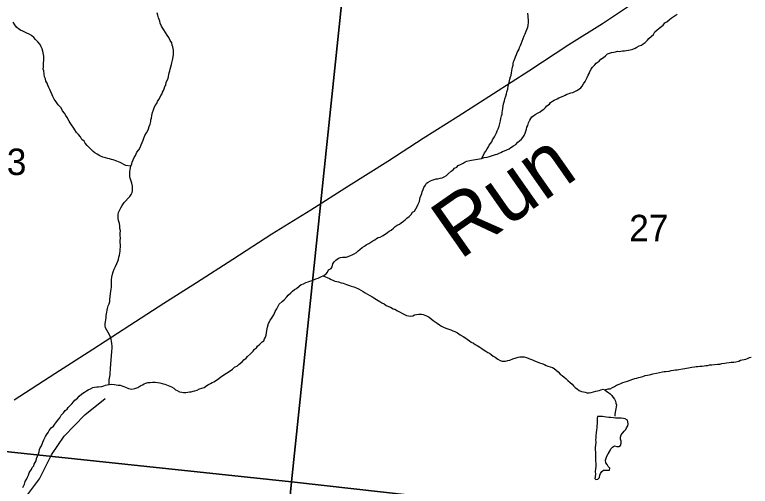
# Model space of a CAD drawing. Extents: x 1310247 to 1664935, y 284496 to 704931.
# Drawn here: x 1488010 to 1494175, y 510491 to 514440 of the extents above; entities that cross this region are included whole.
import ezdxf

# ---------------------------------------------------------------- set-up
doc = ezdxf.new("R2010")
doc.units = 0
for name, color, linetype in [('GM_X_County', 7, 'Continuous'), ('GM_X_County_Subdivision_Text', 7, 'Continuous'), ('GM_X_Minor_Lake_Text', 7, 'Continuous'), ('GM_X_Minor_River', 7, 'Continuous'), ('GM_X_Minor_River_Text', 7, 'Continuous'), ('GM_X_State_Shield', 7, 'Continuous'), ('GM_X_US_Location', 7, 'Continuous')]:
    doc.layers.add(name, color=color, linetype=linetype)

msp = doc.modelspace()

# ---------------------------------------------------------------- linework, layer by layer
at = {"layer": 'GM_X_County'}
for points in [[(1485560.1, 516006.4), (1490846.7, 515461.6), (1490330.6, 510528.2), (1485056.1, 511086.7)], [(1490846.7, 515461.6), (1496329.6, 514931.2), (1495825.8, 509911.6), (1490330.6, 510528.2)], [(1485056.1, 511086.7), (1490330.6, 510528.2), (1489787.4, 504902.9), (1486694.2, 505230.8), (1484474.7, 505338.4)], [(1490330.6, 510528.2), (1495825.8, 509911.6), (1495258.9, 504406.3), (1489787.4, 504902.9)]]:
    msp.add_lwpolyline(points, close=True, dxfattribs=at)
at = {"layer": 'GM_X_County_Subdivision_Text'}
msp.add_lwpolyline([(1488033.7, 510094), (1488042.5, 510123.8), (1488071.6, 510290), (1488089, 510365.9), (1488109.8, 510407.7), (1488218.9, 510554.4), (1488318.8, 510753.5), (1488424.1, 510912.3), (1488598, 511090.1), (1488769.2, 511227.7)], dxfattribs=at)
at = {"layer": 'GM_X_Minor_River'}
msp.add_line((1492872.4, 510557.4), (1492880.1, 510547.1), dxfattribs=at)
msp.add_lwpolyline([(1492880.1, 510547.1), (1492898.3, 510550.6), (1492910.8, 510564.2), (1492915.5, 510584.1), (1492920, 510598), (1492930.6, 510615.7), (1492945, 510625.3), (1492963.1, 510626.7), (1492977.2, 510626.3), (1492995.2, 510625.7), (1492997.8, 510641.7), (1492984.2, 510656.1), (1492976.7, 510672.4), (1492965.2, 510688.8), (1492961.8, 510708.9), (1492966.4, 510726.8), (1492973, 510744.6), (1492983.7, 510762.3), (1492992.2, 510776.1), (1493000.7, 510791.8), (1493007.2, 510805.7), (1493019.7, 510819.3), (1493038.1, 510828.8), (1493058, 510824.2), (1493074.2, 510825.7), (1493088.5, 510833.2), (1493093.1, 510851.1), (1493093.7, 510869.1), (1493088.2, 510885.3), (1493086.8, 510903.4), (1493093.4, 510921.2), (1493106, 510938.9), (1493118.6, 510952.5), (1493131.1, 510966.2), (1493137.5, 510980), (1493148.2, 510997.7), (1493150.7, 511011.6), (1493149.2, 511029.7), (1493145.7, 511043.8), (1493128, 511056.4), (1493114, 511058.8), (1493094, 511061.5), (1493080, 511061.9), (1493065.9, 511062.3), (1493045.8, 511063), (1493027.8, 511065.5), (1493003.8, 511066.2), (1492989.7, 511066.7), (1492969.8, 511071.3), (1492951.8, 511073.9), (1492937.7, 511074.3), (1492917.7, 511076.9), (1492895.6, 511075.6), (1492893.1, 511061.6), (1492892.6, 511045.6), (1492892, 511027.6), (1492891.5, 511013.6), (1492889, 510999.6), (1492888.4, 510981.6), (1492885.8, 510963.7), (1492885, 510937.7), (1492882.3, 510917.7), (1492881.6, 510895.7), (1492879, 510879.7), (1492880.5, 510863.7), (1492877.5, 510831.7), (1492875, 510817.8), (1492876.3, 510795.7), (1492877.6, 510775.6), (1492877, 510757.6), (1492878.5, 510741.5), (1492878, 510725.5), (1492879.3, 510705.4), (1492880.5, 510681.4), (1492880.1, 510667.3), (1492879.6, 510653.3), (1492879.1, 510639.3), (1492876.3, 510613.4), (1492877.7, 510595.3), (1492874.9, 510571.3), (1492872.4, 510557.4)], dxfattribs=at)
at = {"layer": 'GM_X_Minor_River_Text'}
for points in [[(1488995.4, 513205.1), (1489004.1, 513224.8), (1489012.8, 513244.6), (1489021.4, 513260.4), (1489027.8, 513274.2), (1489034.4, 513290), (1489051.1, 513309.5), (1489061.8, 513329.3), (1489070.6, 513351), (1489079.3, 513370.8), (1489085.9, 513390.6), (1489092.5, 513406.5), (1489101.2, 513428.2), (1489114, 513449.9), (1489124.8, 513471.6), (1489131.3, 513485.4), (1489137.9, 513505.2), (1489144.6, 513525.1), (1489151.4, 513546.9), (1489151.8, 513560.9), (1489156.3, 513574.8), (1489159.1, 513596.8), (1489165.9, 513620.6), (1489172.6, 513642.4), (1489179.2, 513660.2), (1489187.9, 513680), (1489200.6, 513697.6), (1489207.1, 513713.5), (1489217.7, 513729.2), (1489230.5, 513750.8), (1489234.9, 513764.7), (1489245.4, 513778.4), (1489249.9, 513792.3), (1489256.4, 513806.1), (1489262.9, 513820), (1489269.5, 513837.8), (1489276, 513851.6), (1489280.8, 513875.5), (1489291.5, 513895.2), (1489296, 513909.1), (1489300.4, 513923), (1489303, 513939), (1489305.5, 513954.9), (1489310.1, 513970.8), (1489312.5, 513984.7), (1489319.2, 514004.6), (1489323.8, 514022.5), (1489326.3, 514036.4), (1489333.1, 514060.2), (1489335.6, 514074.2), (1489338, 514088.1), (1489340.7, 514108.1), (1489341.4, 514128.1), (1489341.8, 514142.1), (1489338.4, 514158.3), (1489336.8, 514172.3), (1489331.3, 514186.5), (1489325.8, 514204.7), (1489314.4, 514225.1), (1489301.2, 514249.6), (1489287.8, 514270), (1489274.5, 514292.5), (1489261.1, 514312.9), (1489247.6, 514329.3), (1489240.1, 514345.6), (1489230.8, 514369.9), (1489225.3, 514386.1), (1489214.2, 514414.5), (1489208.9, 514436.7), (1489205.5, 514454.9)], [(1491924.1, 513237.2), (1491947.7, 513282.6), (1491958.3, 513298.3), (1491968.9, 513316), (1491981.5, 513333.7), (1491988, 513347.5), (1491998.6, 513363.2), (1492009.1, 513376.9), (1492015.6, 513392.7), (1492030.5, 513416.3), (1492041.1, 513434), (1492049.7, 513449.8), (1492054.3, 513467.7), (1492062.9, 513485.4), (1492069.7, 513507.3), (1492076.4, 513529.1), (1492081.2, 513553), (1492085.8, 513570.9), (1492090.6, 513594.8), (1492095.1, 513608.7), (1492095.6, 513622.7), (1492098.1, 513638.6), (1492100.7, 513654.6), (1492105.3, 513674.5), (1492108, 513694.4), (1492114.9, 513720.2), (1492119.4, 513736.1), (1492126.2, 513758), (1492130.8, 513777.9), (1492135.4, 513793.8), (1492142.2, 513817.6), (1492145.1, 513845.5), (1492154, 513871.3), (1492161, 513901.2), (1492165.7, 513919), (1492170.2, 513934.9), (1492172.8, 513952.9), (1492177.4, 513970.8), (1492179.9, 513986.7), (1492182.4, 514000.7), (1492187, 514016.6), (1492189.4, 514030.5), (1492191.9, 514044.5), (1492196.4, 514058.3), (1492207.4, 514088.1), (1492216.1, 514107.8), (1492222.6, 514123.7), (1492229.1, 514137.5), (1492237.7, 514153.2), (1492242.2, 514167.1), (1492248.7, 514183), (1492255.2, 514196.8), (1492264, 514218.6), (1492272.8, 514242.3), (1492281.5, 514262.1), (1492288.1, 514279.9), (1492296.8, 514301.7), (1492305.6, 514323.5), (1492310.1, 514337.4), (1492314.6, 514351.2), (1492317.5, 514379.2), (1492316.2, 514401.3), (1492314.7, 514415.4), (1492313.1, 514429.4), (1492309.9, 514453.6)], [(1492872.3, 514019.5), (1492884.8, 514035.2), (1492907.5, 514052.5), (1492924.1, 514068), (1492944.7, 514083.4), (1492961.1, 514094.9), (1492977.8, 514112.4), (1492994.1, 514118), (1493012.3, 514123.4), (1493030.5, 514126.9), (1493046.7, 514130.4), (1493062.9, 514133.9), (1493076.9, 514133.4), (1493091.1, 514135), (1493105.2, 514136.6), (1493121.3, 514138.1), (1493135.4, 514139.7), (1493153.6, 514143.1), (1493167.8, 514146.7), (1493190.1, 514152), (1493210.4, 514159.4), (1493224.8, 514169), (1493243.2, 514178.4), (1493263.5, 514185.8), (1493278, 514197.4), (1493294.4, 514208.9), (1493315.2, 514228.3), (1493325.7, 514242), (1493348.4, 514261.3), (1493362.9, 514274.9), (1493375.7, 514296.5), (1493392.3, 514312.1), (1493410.9, 514327.5), (1493443.9, 514352.5), (1493460.6, 514372.1), (1493476.9, 514379.6), (1493497.7, 514401), (1493512.1, 514410.6), (1493528.5, 514422.1), (1493563.5, 514445)], [(1488982.3, 513173.4), (1488940.3, 513178.7), (1488924.5, 513187.2), (1488906.7, 513195.8), (1488892.8, 513202.2), (1488865.1, 513215.1), (1488835.3, 513224), (1488821.4, 513228.5), (1488805.5, 513233), (1488789.5, 513237.5), (1488771.6, 513242), (1488749.7, 513248.7), (1488723.9, 513259.5), (1488700.3, 513272.2), (1488682.5, 513282.8), (1488668.9, 513295.3), (1488651.3, 513311.8), (1488631.9, 513330.5), (1488616.3, 513345), (1488600.8, 513363.5), (1488591.3, 513381.8), (1488573.7, 513396.4), (1488560.4, 513418.8), (1488545, 513437.3), (1488529.4, 513453.8), (1488514.1, 513476.3), (1488504.5, 513490.7), (1488485.3, 513517.3), (1488475.8, 513533.6), (1488466.3, 513549.9), (1488449.2, 513578.5), (1488437.7, 513596.9), (1488426.3, 513615.3), (1488410.9, 513635.8), (1488399.6, 513660.2), (1488374.3, 513685), (1488359, 513709.5), (1488341.8, 513734.1), (1488330.5, 513756.5), (1488324.9, 513770.7), (1488313.6, 513795.1), (1488304.3, 513815.4), (1488296.7, 513829.6), (1488287.3, 513850), (1488281.8, 513866.2), (1488272.3, 513882.5), (1488267, 513902.7), (1488259.5, 513921), (1488256.3, 513943.1), (1488255.1, 513969.2), (1488249.5, 513983.4), (1488250.2, 514003.4), (1488251, 514027.4), (1488251.5, 514041.4), (1488253.9, 514055.4), (1488254.7, 514077.4), (1488253.2, 514093.5), (1488251.6, 514107.5), (1488248.1, 514121.7), (1488246.5, 514135.7), (1488241.1, 514153.9), (1488231.7, 514172.3), (1488224.2, 514190.5), (1488204.9, 514213.1), (1488185.5, 514233.8), (1488170, 514250.3), (1488152.3, 514264.9), (1488132.7, 514277.5), (1488112.9, 514286.1), (1488095.1, 514294.7), (1488079.2, 514301.2), (1488059.5, 514311.8), (1488043.7, 514320.3), (1488024.1, 514336.9), (1488010.7, 514355.4), (1487997.3, 514377.8)], [(1491388.8, 512847), (1491401.8, 512876.6), (1491406.4, 512894.5), (1491408.9, 512908.5), (1491417.6, 512928.2), (1491422.1, 512944.1), (1491424.6, 512958.1), (1491433.2, 512975.8), (1491439.8, 512993.7), (1491452.5, 513013.3), (1491461.1, 513029.1), (1491475.5, 513038.7), (1491493.9, 513050.1), (1491510.2, 513055.6), (1491526.5, 513061.1), (1491542.7, 513064.6), (1491556.8, 513066.2), (1491575, 513071.7), (1491593.2, 513073.1), (1491609.6, 513082.6), (1491630, 513094), (1491644.5, 513107.6), (1491669.4, 513128.9), (1491685.8, 513140.4), (1491696.3, 513154.1), (1491714.7, 513163.5), (1491727.2, 513177.2), (1491745.6, 513186.6), (1491770.1, 513197.9), (1491786.5, 513207.4), (1491800.7, 513213), (1491825.1, 513220.3), (1491839.2, 513221.8), (1491855.4, 513225.3), (1491873.6, 513228.8), (1491905.9, 513233.8), (1491924.1, 513237.2), (1491944.5, 513244.6), (1491970.7, 513247.8), (1491988.9, 513253.3), (1492005.2, 513258.8), (1492023.5, 513264.2), (1492039.7, 513269.8), (1492053.9, 513273.3), (1492070.2, 513280.8), (1492084.5, 513286.4), (1492098.8, 513294), (1492115, 513299.5), (1492153.8, 513316.3), (1492168.2, 513327.9), (1492190.8, 513343.2), (1492211.3, 513354.6), (1492226, 513372.2), (1492242.4, 513383.7), (1492257, 513399.3), (1492269.5, 513413), (1492280.1, 513428.7), (1492288.8, 513448.4), (1492295.4, 513466.3), (1492299.9, 513482.1), (1492302.5, 513498.1), (1492311, 513513.9), (1492317.7, 513533.7), (1492326.5, 513557.5), (1492335, 513571.2), (1492343.5, 513585), (1492357.8, 513592.6), (1492372.3, 513604.1), (1492398.9, 513619.3), (1492413.2, 513626.9), (1492431.7, 513640.4), (1492446.1, 513650), (1492458.6, 513663.6), (1492469.1, 513677.3), (1492491.7, 513690.6), (1492502.2, 513706.3), (1492518.6, 513715.8), (1492532.9, 513723.4), (1492555.5, 513736.8), (1492571.8, 513744.3), (1492606.5, 513759.2), (1492622.8, 513766.7), (1492637.1, 513774.3), (1492657.4, 513779.7), (1492671.6, 513785.3), (1492687.8, 513788.8), (1492706.2, 513798.2), (1492722.5, 513805.7), (1492736.8, 513813.3), (1492755.4, 513828.8), (1492765.9, 513842.5), (1492776.6, 513862.2), (1492791.3, 513881.8), (1492799.9, 513897.5), (1492808.5, 513915.3), (1492817.1, 513933.1), (1492823.7, 513948.9), (1492830.2, 513964.7), (1492840.9, 513984.4), (1492851.6, 514002.1), (1492872.3, 514019.5)], [(1488803.3, 511343.6), (1488802.6, 511381.7), (1488805, 511395.7), (1488807.5, 511409.6), (1488810, 511423.6), (1488810.6, 511443.6), (1488813.4, 511465.6), (1488814, 511485.6), (1488814.7, 511505.6), (1488815.3, 511523.6), (1488817.9, 511541.5), (1488818.4, 511557.6), (1488821.1, 511577.5), (1488821.7, 511595.5), (1488824.1, 511609.5), (1488824.7, 511625.5), (1488827.3, 511643.4), (1488828, 511665.5), (1488824.7, 511685.6), (1488821.4, 511707.7), (1488817.9, 511723.9), (1488812.4, 511740.1), (1488806.8, 511754.3), (1488793.6, 511778.7), (1488782.2, 511799.1), (1488770.7, 511817.5), (1488767.3, 511833.6), (1488767.9, 511853.6), (1488770.4, 511867.6), (1488773, 511885.5), (1488775.7, 511905.5), (1488776.2, 511921.5), (1488781.1, 511949.4), (1488785.7, 511965.3), (1488788.1, 511979.2), (1488794.9, 512001.1), (1488801.5, 512018.9), (1488806.2, 512038.8), (1488808.8, 512056.8), (1488811.6, 512080.7), (1488814.4, 512104.7), (1488817, 512122.6), (1488819.6, 512140.6), (1488820.2, 512158.6), (1488820.8, 512178.6), (1488821.6, 512200.6), (1488822.2, 512220.6), (1488825, 512242.6), (1488829.8, 512266.5), (1488834.5, 512288.4), (1488843.2, 512308.1), (1488854, 512331.8), (1488866.9, 512357.5), (1488875.6, 512375.3), (1488880, 512389.1), (1488882.7, 512409.1), (1488889.3, 512426.9), (1488891.9, 512442.9), (1488894.5, 512460.8), (1488894.9, 512474.8), (1488895.7, 512496.9), (1488896.1, 512510.9), (1488894.9, 512535), (1488895.4, 512549), (1488896, 512569), (1488894.8, 512591.1), (1488895.4, 512611.1), (1488896, 512629.1), (1488892.7, 512649.2), (1488891.4, 512671.3), (1488888, 512691.5), (1488880.8, 512715.7), (1488877.4, 512735.8), (1488876, 512751.9), (1488876.4, 512765.9), (1488881, 512783.8), (1488887.6, 512801.7), (1488898.4, 512823.4), (1488911.1, 512843), (1488928, 512866.5), (1488938.5, 512880.2), (1488961.3, 512903.6), (1488973.9, 512917.2), (1488986.5, 512934.9), (1488995.1, 512952.6), (1488997.6, 512966.6), (1488998.2, 512986.6), (1488996.8, 513004.7), (1488991.6, 513028.9), (1488984.4, 513055.1), (1488978.9, 513071.3), (1488975.4, 513085.5), (1488974, 513103.5), (1488974.6, 513121.6), (1488977.3, 513143.5), (1488979.8, 513157.5), (1488982.3, 513173.4), (1488990.9, 513191.2), (1488995.4, 513205.1)], [(1489877.5, 511501), (1489892, 511514.5), (1489916.7, 511533.8), (1489931.4, 511551.4), (1489949.9, 511564.8), (1489962.4, 511578.5), (1489985.3, 511601.8), (1490008.1, 511623.2), (1490020.7, 511638.8), (1490037.1, 511650.3), (1490045.6, 511664.1), (1490064.3, 511681.5), (1490083, 511701), (1490097.4, 511710.6), (1490104, 511726.4), (1490112.4, 511740.2), (1490117, 511756.1), (1490119.7, 511776), (1490122.3, 511796), (1490126.8, 511809.9), (1490129.3, 511823.8), (1490138.3, 511853.6), (1490144.8, 511867.4), (1490151.3, 511881.2), (1490161.8, 511896.9), (1490170.3, 511910.7), (1490180.9, 511926.4), (1490187.4, 511942.2), (1490193.9, 511956.1), (1490206.7, 511977.7), (1490219.5, 511999.3), (1490228.1, 512017.1), (1490252.9, 512038.4), (1490267.5, 512054), (1490292.4, 512077.3), (1490302.9, 512091), (1490323.6, 512110.3), (1490338.1, 512123.9), (1490354.7, 512139.5), (1490373.1, 512148.9), (1490395.8, 512166.2), (1490412.3, 512179.8), (1490430.6, 512187.2), (1490449, 512196.7), (1490469.3, 512202), (1490483.5, 512207.6), (1490503.9, 512215), (1490534.5, 512228.1), (1490552.7, 512233.5), (1490581.3, 512246.7), (1490595.6, 512254.3), (1490620.2, 512269.5), (1490632.8, 512285.2), (1490641.4, 512302.9), (1490661.9, 512316.3), (1490670.4, 512330.1), (1490677.3, 512353.9), (1490687.8, 512369.6), (1490702.4, 512385.2), (1490723, 512400.6), (1490741.3, 512408.1), (1490757.5, 512409.6), (1490773.5, 512409.1), (1490787.6, 512410.6), (1490803.8, 512414.2), (1490824.2, 512423.5), (1490838.5, 512429.1), (1490854.8, 512436.6), (1490875.3, 512450), (1490889.8, 512461.6), (1490904.2, 512473.2), (1490922.9, 512490.6), (1490941.4, 512502.1), (1490955.8, 512513.7), (1490978.3, 512525), (1490994.7, 512534.5), (1491011.1, 512546), (1491027.5, 512555.5), (1491041.9, 512565.1), (1491056.3, 512574.7), (1491074.5, 512578.1), (1491092.9, 512589.6), (1491115.5, 512602.9), (1491134, 512616.4), (1491148.5, 512628), (1491166.9, 512637.4), (1491185.5, 512652.9), (1491200, 512666.5), (1491216.4, 512678), (1491234.8, 512685.4), (1491249.2, 512697), (1491267.8, 512712.5), (1491284.2, 512722), (1491296.7, 512735.6), (1491317.3, 512751), (1491331.9, 512766.6), (1491344.6, 512786.2), (1491361, 512795.7), (1491373.6, 512813.4), (1491384.3, 512833.1), (1491388.8, 512847)], [(1490595.6, 512254.3), (1490649.1, 512230.6), (1490662.9, 512224.1), (1490676.8, 512217.7), (1490692.6, 512209.2), (1490710.6, 512206.6), (1490724.5, 512202.2), (1490746.4, 512195.5), (1490762.3, 512191), (1490776.2, 512186.6), (1490792.1, 512180.1), (1490816, 512173.4), (1490829.8, 512166.9), (1490851.7, 512160.2), (1490867.6, 512155.8), (1490891.4, 512145), (1490911.1, 512132.4), (1490930.9, 512123.8), (1490948.5, 512111.2), (1490968.3, 512100.5), (1490986, 512090), (1491003.8, 512079.4), (1491021.5, 512068.9), (1491043.2, 512056.2), (1491070.7, 512039.3), (1491086.4, 512026.8), (1491106.3, 512020.2), (1491123.9, 512005.6), (1491143.7, 511997), (1491159.6, 511992.5), (1491183.2, 511977.8), (1491197.2, 511973.3), (1491218.8, 511960.6), (1491240.6, 511949.9), (1491260.3, 511937.3), (1491278.1, 511928.8), (1491293.9, 511922.2), (1491311.9, 511919.7), (1491329.9, 511917.1), (1491346.1, 511918.6), (1491360.4, 511926.2), (1491378.6, 511929.7), (1491396.8, 511933.1), (1491418.9, 511932.4), (1491434.8, 511929.9), (1491448.7, 511923.5), (1491462.6, 511919.1), (1491484.3, 511906.4), (1491502, 511893.8), (1491517.6, 511879.3), (1491533.3, 511868.8), (1491551, 511856.2), (1491570.6, 511843.6), (1491588.4, 511833), (1491604.1, 511822.6), (1491624, 511815.9), (1491641.8, 511809.4), (1491665.7, 511800.6), (1491683.5, 511792.1), (1491699.4, 511787.6), (1491721.1, 511774.9), (1491744.7, 511760.1), (1491768.3, 511745.4), (1491790, 511730.7), (1491803.7, 511722.2), (1491823.4, 511709.6), (1491837.1, 511699.2), (1491854.9, 511688.6), (1491870.6, 511678.1), (1491886.4, 511669.6), (1491908, 511654.9), (1491925.7, 511644.4), (1491945.4, 511631.7), (1491959.2, 511623.3), (1491976.9, 511612.7), (1491990.8, 511606.3), (1492004.5, 511595.9), (1492020.1, 511581.4), (1492035.9, 511572.9), (1492059.5, 511556.1), (1492079.1, 511543.5), (1492095.1, 511539), (1492109.1, 511538.5), (1492123.2, 511540.1), (1492143.4, 511543.5), (1492159.6, 511547), (1492186.1, 511558.2), (1492212.6, 511567.4), (1492230.8, 511572.9), (1492245, 511576.5), (1492261.1, 511576), (1492279.1, 511575.4), (1492299, 511568.8), (1492318.9, 511562.2), (1492332.7, 511555.7), (1492350.6, 511549.2), (1492366.5, 511542.7), (1492388.3, 511534), (1492408.1, 511525.3), (1492428, 511518.7), (1492449.8, 511510)], [(1492957.2, 511300.1), (1492985.6, 511307.2), (1493001.7, 511308.7), (1493020.1, 511318.2), (1493038.5, 511327.6), (1493054.9, 511337.2), (1493077.3, 511346.5), (1493091.6, 511352.1), (1493105.9, 511359.6), (1493126.2, 511365), (1493146.5, 511372.4), (1493168.8, 511379.7), (1493191.2, 511387.1), (1493207.4, 511392.6), (1493223.6, 511396.1), (1493237.9, 511401.6), (1493252.1, 511405.2), (1493274.3, 511410.5), (1493294.7, 511417.9), (1493312.9, 511421.4), (1493341.2, 511428.5), (1493357.5, 511434), (1493389.8, 511439), (1493414.1, 511444.3), (1493438.4, 511449.6), (1493452.5, 511451.1), (1493466.6, 511452.7), (1493494.9, 511455.8), (1493511.1, 511461.4), (1493531.3, 511462.7), (1493547.4, 511466.2), (1493561.6, 511467.8), (1493575.7, 511469.4), (1493606, 511474.5), (1493626.2, 511477.9), (1493640.4, 511481.4), (1493656.5, 511482.9), (1493670.7, 511486.5), (1493684.8, 511488.1), (1493707, 511491.4), (1493721.1, 511493), (1493735.2, 511494.5), (1493753.4, 511496), (1493773.5, 511497.4), (1493789.7, 511500.9), (1493803.8, 511502.4), (1493819.9, 511503.9), (1493834.1, 511507.5), (1493854.3, 511508.9), (1493874.5, 511512.3), (1493900.6, 511513.5), (1493920.8, 511514.9), (1493937, 511518.4), (1493961.2, 511521.6), (1493975.4, 511525.2), (1493999.5, 511526.5), (1494015.7, 511530), (1494037.9, 511531.3), (1494054.1, 511534.8), (1494078.3, 511540.1), (1494094.7, 511547.6), (1494137.1, 511556.3), (1494153.4, 511561.8), (1494167.7, 511569.4), (1494183.9, 511572.9)], [(1488194.1, 510723.2), (1488209.4, 510762.8), (1488214, 510778.7), (1488216.7, 510798.7), (1488223.2, 510814.5), (1488233.8, 510830.2), (1488246.9, 510861.9), (1488253.5, 510879.7), (1488268.5, 510907.3), (1488277, 510923.1), (1488289.7, 510942.7), (1488300.3, 510958.4), (1488317.1, 510981.9), (1488335.7, 510995.4), (1488346.2, 511011.1), (1488363.1, 511034.6), (1488373.6, 511048.3), (1488388.2, 511063.9), (1488400.9, 511085.5), (1488419.7, 511105), (1488432.4, 511124.6), (1488450.8, 511136.1), (1488457.3, 511149.9), (1488476, 511167.4), (1488488.6, 511183), (1488503.1, 511198.6), (1488513.6, 511212.3), (1488536.3, 511229.6), (1488550.9, 511245.2), (1488571.6, 511264.6), (1488594.2, 511280), (1488610.6, 511289.5), (1488625, 511299), (1488645.4, 511308.4), (1488663.8, 511317.9), (1488680, 511321.4), (1488698.1, 511322.8), (1488712.3, 511324.4), (1488740.5, 511327.5), (1488756.7, 511333.1), (1488771, 511338.6), (1488785.2, 511342.2), (1488803.3, 511343.6), (1488823.4, 511345), (1488845.5, 511342.3), (1488861.5, 511339.9), (1488877.5, 511339.4), (1488893.5, 511336.9), (1488909.4, 511332.4), (1488925.4, 511327.9), (1488939.2, 511321.4), (1488965, 511310.6), (1488978.9, 511306.2), (1488992.9, 511305.8), (1489017.2, 511309), (1489041.6, 511318.3), (1489066.3, 511335.6), (1489080.5, 511341.1), (1489094.8, 511348.7), (1489109.1, 511354.3), (1489127.3, 511359.7), (1489145.5, 511361.2), (1489165.6, 511362.6), (1489187.7, 511361.9), (1489205.8, 511361.3), (1489227.7, 511356.6), (1489245.6, 511352.1), (1489267.6, 511347.4), (1489281.4, 511341), (1489295.4, 511336.5), (1489309.2, 511330.1), (1489325.1, 511323.6), (1489342.8, 511313), (1489358.4, 511298.5), (1489372.3, 511292.1), (1489390.1, 511283.5), (1489410, 511278.9), (1489424, 511276.5), (1489444.1, 511277.8), (1489462.3, 511279.3), (1489476.4, 511280.9), (1489490.5, 511282.4), (1489504.7, 511288), (1489518.9, 511289.6), (1489539.1, 511295), (1489559.6, 511306.4), (1489577.9, 511311.8), (1489598.2, 511319.2), (1489620.8, 511334.5), (1489635.2, 511344.1), (1489651.5, 511351.6), (1489665.8, 511359.2), (1489680.1, 511366.8), (1489708.9, 511385.9), (1489735.7, 511405.1), (1489762.4, 511424.3), (1489785, 511439.7), (1489807.6, 511453), (1489836.3, 511472.2), (1489853, 511489.7), (1489877.5, 511501)], [(1492449.8, 511510), (1492465.6, 511503.5), (1492479.5, 511497.1), (1492497.4, 511492.5), (1492517.3, 511485.9), (1492533.1, 511477.4), (1492548.7, 511464.9), (1492566.3, 511448.4), (1492581.7, 511429.8), (1492599.5, 511419.3), (1492615.1, 511404.8), (1492628.8, 511394.3), (1492646.3, 511375.8), (1492665.8, 511359.1), (1492681.5, 511346.6), (1492695.1, 511332.2), (1492708.6, 511317.8), (1492726.3, 511303.2), (1492742, 511292.7), (1492759.8, 511286.1), (1492777.8, 511281.6), (1492791.8, 511279.1), (1492805.7, 511274.7), (1492823.8, 511274.1), (1492842, 511277.6), (1492860.1, 511281), (1492880.4, 511286.4), (1492894.6, 511290), (1492908.8, 511293.6), (1492923, 511299.1), (1492941.3, 511304.6), (1492955.2, 511298.1), (1492972.8, 511285.6), (1492986.6, 511277.1), (1493002.3, 511264.6), (1493013.9, 511250.3), (1493025.4, 511235.9), (1493037, 511221.5), (1493044.5, 511205.2), (1493049.9, 511187), (1493053.5, 511172.9), (1493051, 511157), (1493048.4, 511139), (1493045.9, 511125.1), (1493043.4, 511111.1), (1493040.8, 511093.2), (1493040.4, 511079.1)], [(1488077.6, 510482.4), (1488092.5, 510508), (1488099.3, 510531.8), (1488112.1, 510553.5), (1488118.6, 510567.3), (1488125.1, 510583.1), (1488131.8, 510603), (1488140.3, 510616.7), (1488150.9, 510632.4), (1488157.4, 510648.2), (1488169.9, 510661.9), (1488174.5, 510677.8), (1488189.5, 510705.4), (1488194.1, 510723.2)]]:
    msp.add_lwpolyline(points, dxfattribs=at)
at = {"layer": 'GM_X_State_Shield'}
msp.add_lwpolyline([(1488005.1, 511216.3), (1488347.7, 511435.1), (1488665.9, 511640.3), (1488975.9, 511839.8), (1489259.4, 512023.8), (1489534.7, 512198), (1489838.6, 512393.5), (1490165, 512606.6), (1490493, 512807.6), (1490809.1, 513006.9), (1491137.3, 513214), (1491433.1, 513405.7), (1491726.7, 513591.5), (1492022.4, 513779.3), (1492320.1, 513970.9), (1492654.8, 514191.9), (1492938.1, 514367.8), (1493205.4, 514546.2)], dxfattribs=at)

# ---------------------------------------------------------------- texts
at = {"layer": 'GM_X_Minor_Lake_Text'}
msp.add_text('Run', height=500.03, rotation=34.9659, dxfattribs=at).set_placement((1491740.7, 512382.1))
at = {"layer": 'GM_X_US_Location'}
for s, p in [('33', (1487779.6, 513098.1)), ('27', (1493160.8, 512543.7))]:
    msp.add_text(s, height=221, rotation=0.00001, dxfattribs=at).set_placement(p)

doc.saveas('drawing.dxf')
